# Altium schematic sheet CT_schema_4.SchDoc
size 328 x 258 mm
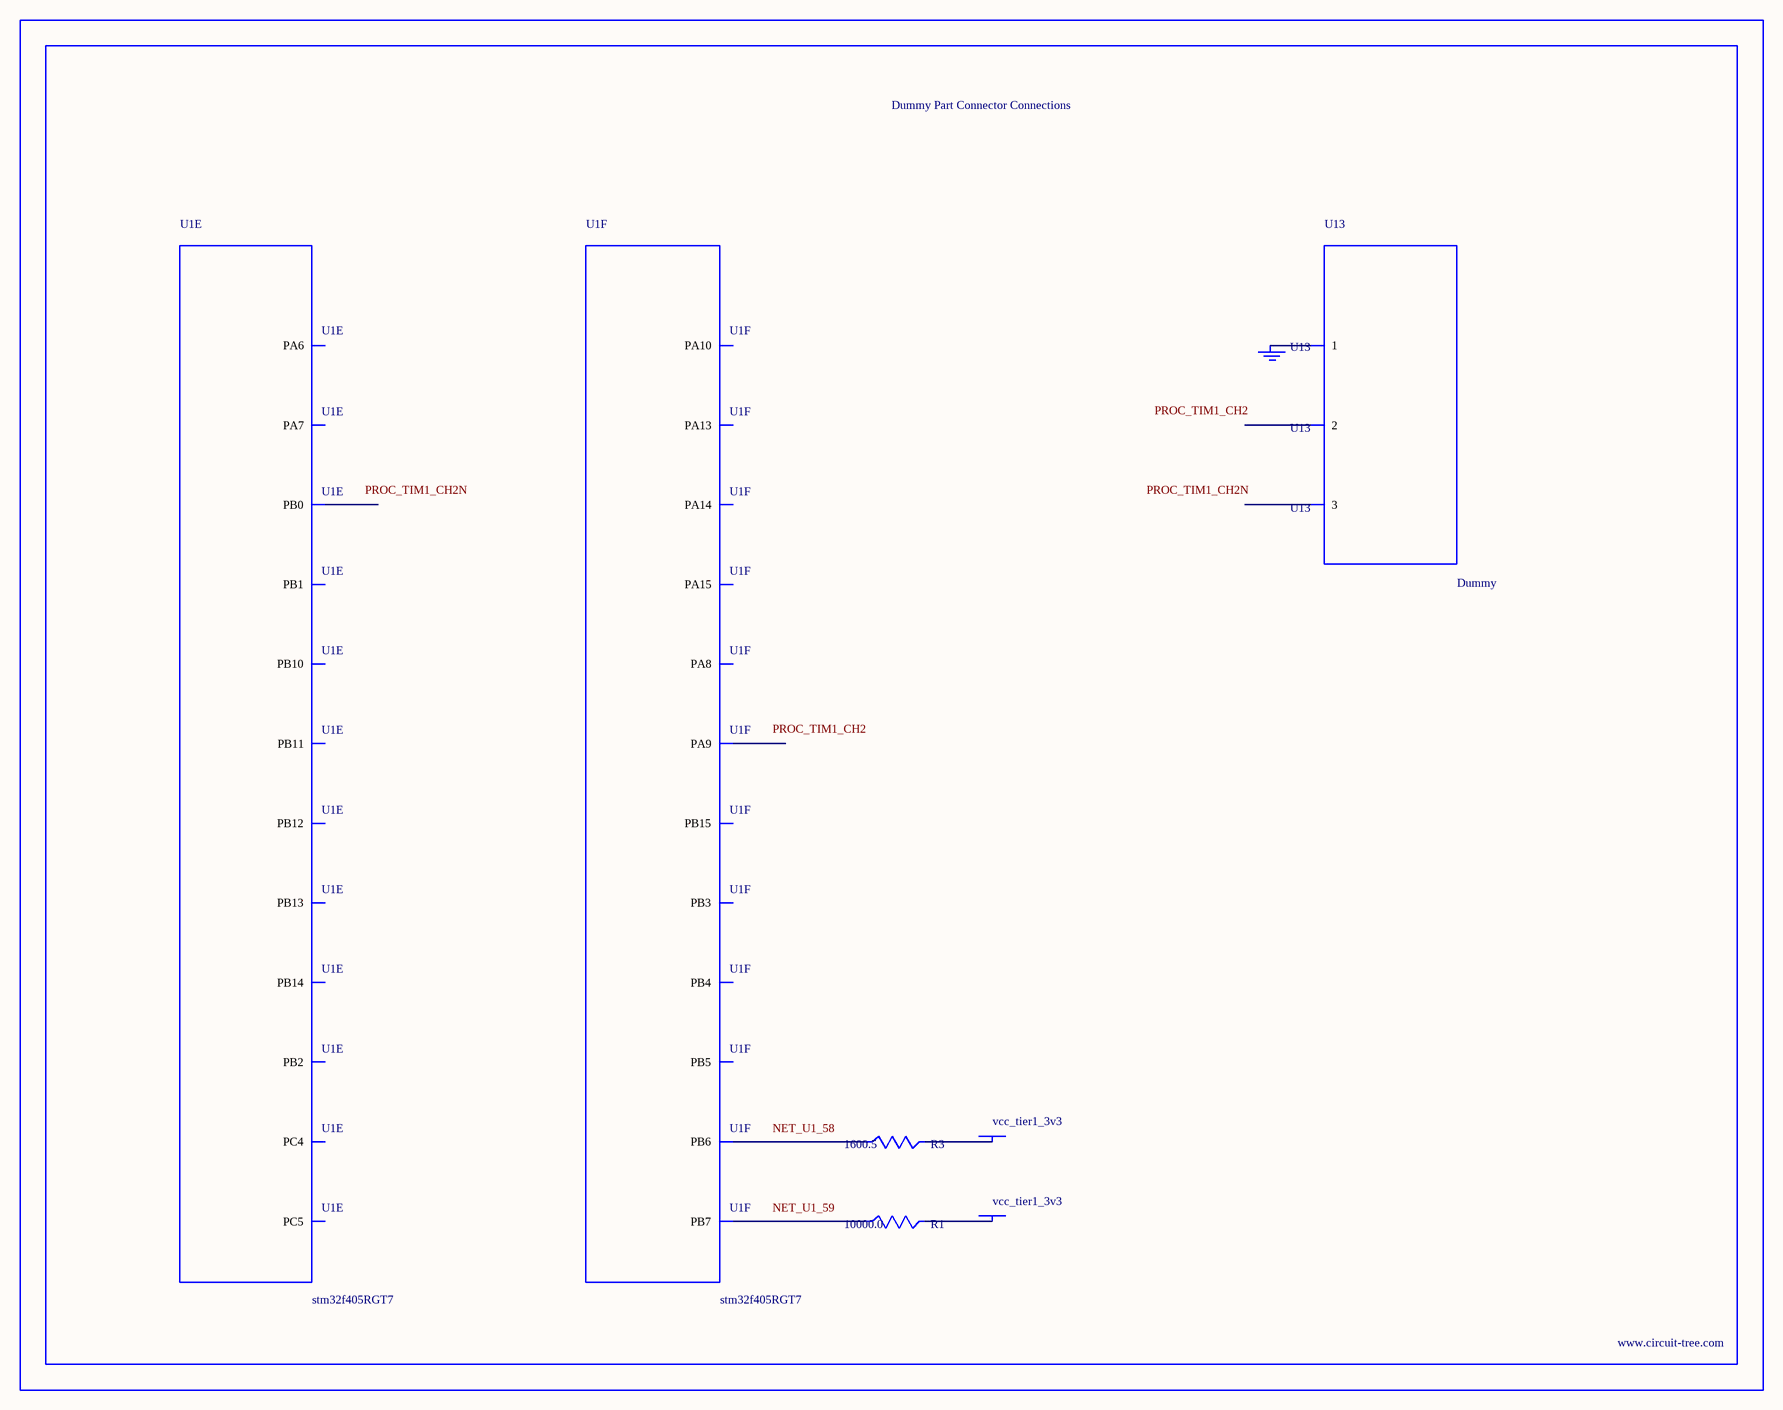
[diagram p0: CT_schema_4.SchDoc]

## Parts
BORDER3  (no value)
GND_INSTANCE_3_0  (no value)
POWER_INSTANCE_3_0  vcc_tier1_3v3
POWER_INSTANCE_3_1  vcc_tier1_3v3
R1  10000.0  [R0603]
R3  1600.5  [R0603]
U1  stm32f405RGT7  [LQFP64]  (parts E,F of 6)
U13  Dummy  [DUMMY_PACKAGE_149]

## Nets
NetGND_INSTANCE_3_0_0: GND_INSTANCE_3_0.0(GND) U13.1
NetPOWER_INSTANCE_3_0_0: POWER_INSTANCE_3_0.0(PWR) R3.2
NetPOWER_INSTANCE_3_1_0: POWER_INSTANCE_3_1.0(PWR) R1.2
NetR1_1: R1.1 U1.59(PB7)
NetR3_1: R3.1 U1.58(PB6)

Not connected (* = marked no-connect by the designer): U1 22(PA6) 23(PA7) 24(PC4) 25(PC5) 26(PB0) 27(PB1) 28(PB2) 29(PB10) 30(PB11) 33(PB12) 34(PB13) 35(PB14) 36(PB15) 41(PA8) 42(PA9) 43(PA10) 46(PA13) 49(PA14) 50(PA15) 55(PB3) 56(PB4) 57(PB5); U13 2 3

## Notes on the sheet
- Labels drawn without touching a wire or pin: NET_U1_58, NET_U1_59, PROC_TIM1_CH2, PROC_TIM1_CH2N

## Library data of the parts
BORDER3 = BORDER_PAGE3
GND_INSTANCE_3_0 = GND
POWER_INSTANCE_3_0 POWER_INSTANCE_3_1 = PWR
R1 = RC0603JR-0710KL
R3 = R3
